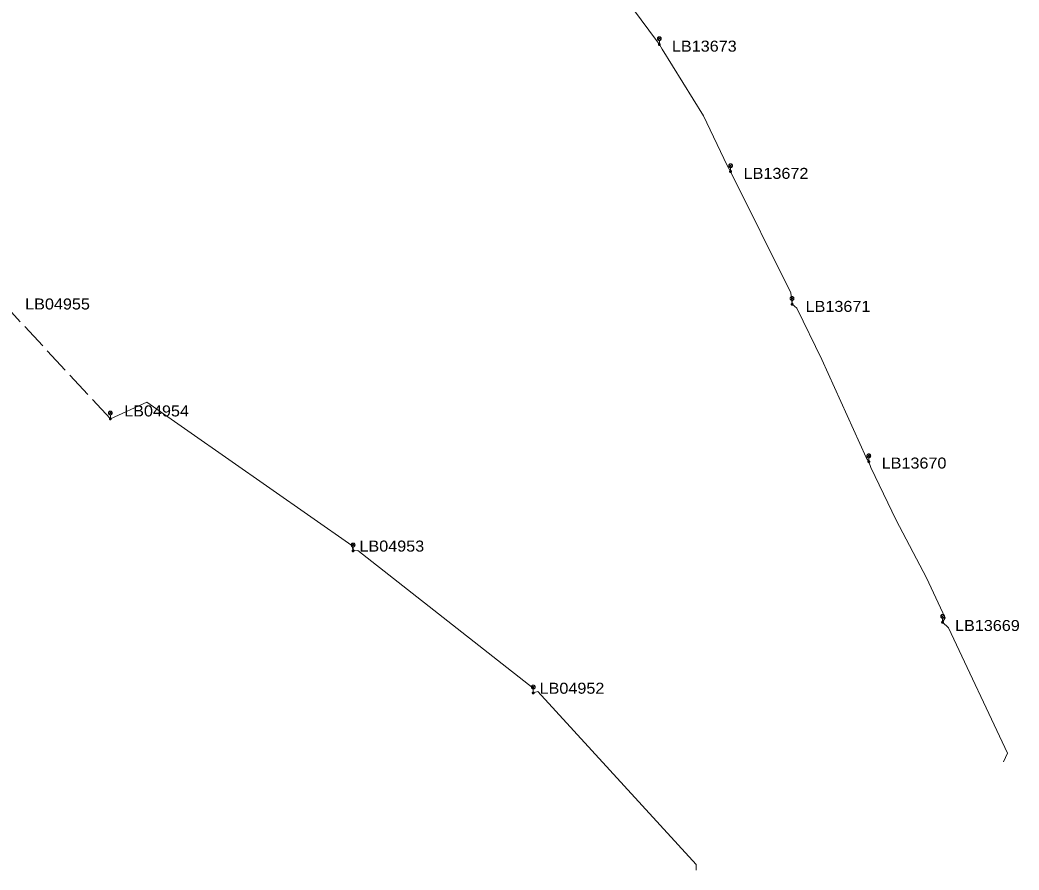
# Model space of a CAD drawing. Extents: x -690018 to -689415, y -972457 to -972107.
# Drawn here: x -689842.5 to -689645.5, y -972456.7 to -972289.3 of the extents above; entities that cross this region are included whole.
import ezdxf

# ---------------------------------------------------------------- set-up
doc = ezdxf.new("R2010")
doc.units = 0
doc.header["$LTSCALE"] = 0.87
doc.linetypes.add('LONG_DASHED', pattern=[7.5, 6, -1.5])
doc.layers.add('1', color=7, linetype='Continuous', lineweight=13)

msp = doc.modelspace()

# ---------------------------------------------------------------- linework, layer by layer
at = {"layer": '1'}
for p, q in [((-689716.685, -972292.665), (-689716.155, -972293.195)), ((-689716.685, -972293.195), (-689716.155, -972292.665)), ((-689716.42, -972294.08), (-689716.42, -972293.305)), ((-689702.635, -972317.705), (-689702.105, -972318.235)), ((-689702.635, -972318.235), (-689702.105, -972317.705)), ((-689702.37, -972319.12), (-689702.37, -972318.345)), ((-689690.515, -972343.865), (-689689.985, -972344.395)), ((-689690.515, -972344.395), (-689689.985, -972343.865)), ((-689690.25, -972345.28), (-689690.25, -972344.505)), ((-689824.905, -972366.425), (-689824.375, -972366.955)), ((-689824.905, -972366.955), (-689824.375, -972366.425)), ((-689824.64, -972367.84), (-689824.64, -972367.065)), ((-689675.395, -972374.875), (-689674.865, -972375.405)), ((-689675.395, -972375.405), (-689674.865, -972374.875)), ((-689675.13, -972376.29), (-689675.13, -972375.515)), ((-689777.048, -972392.422), (-689776.518, -972392.952)), ((-689777.048, -972392.952), (-689776.518, -972392.422)), ((-689776.783, -972393.837), (-689776.783, -972393.062)), ((-689660.845, -972406.495), (-689660.315, -972407.025)), ((-689660.845, -972407.025), (-689660.315, -972406.495)), ((-689660.58, -972407.91), (-689660.58, -972407.135)), ((-689741.535, -972420.425), (-689741.005, -972420.955)), ((-689741.535, -972420.955), (-689741.005, -972420.425)), ((-689741.27, -972421.84), (-689741.27, -972421.065))]:
    msp.add_line(p, q, dxfattribs=at)
at = {"layer": '1', "linetype": 'LONG_DASHED'}
msp.add_line((-689824.64, -972367.84), (-689844.111, -972346.859), dxfattribs=at)
at = {"layer": '1'}
for points in [[(-689736.081, -972268.142), (-689735.301, -972268.549), (-689716.979, -972293.281), (-689716.42, -972294.08)], [(-689716.42, -972294.08), (-689715.873, -972295.023), (-689707.698, -972308.128), (-689703.076, -972317.918), (-689702.37, -972319.12)], [(-689702.37, -972319.12), (-689690.468, -972342.995), (-689690.25, -972345.28)], [(-689690.25, -972345.28), (-689689.336, -972346.046), (-689684.401, -972356.184), (-689675.628, -972375.448), (-689675.13, -972376.29)], [(-689776.783, -972393.837), (-689777.015, -972392.807), (-689817.464, -972364.529), (-689824.64, -972367.84)], [(-689675.13, -972376.29), (-689674.698, -972377.406), (-689669.714, -972387.821), (-689663.787, -972399.156), (-689660.107, -972407.016), (-689660.58, -972407.91)], [(-689741.27, -972421.84), (-689741.27, -972420.888), (-689775.836, -972393.792), (-689776.783, -972393.837)], [(-689660.58, -972407.91), (-689659.447, -972409.021), (-689647.784, -972433.708), (-689648.57, -972435.43)], [(-689709.167, -972456.73), (-689709.167, -972455.675), (-689740.356, -972421.577), (-689741.27, -972421.84)]]:
    msp.add_lwpolyline(points, dxfattribs=at)
for points in [[(-689716.045, -972292.93), (-689716.051, -972292.865), (-689716.068, -972292.802), (-689716.095, -972292.742), (-689716.133, -972292.689), (-689716.179, -972292.643), (-689716.232, -972292.605), (-689716.292, -972292.578), (-689716.355, -972292.561), (-689716.42, -972292.555), (-689716.485, -972292.561), (-689716.548, -972292.578), (-689716.608, -972292.605), (-689716.661, -972292.643), (-689716.707, -972292.689), (-689716.745, -972292.742), (-689716.772, -972292.802), (-689716.789, -972292.865), (-689716.795, -972292.93), (-689716.789, -972292.995), (-689716.772, -972293.058), (-689716.745, -972293.118), (-689716.707, -972293.171), (-689716.661, -972293.217), (-689716.608, -972293.255), (-689716.548, -972293.282), (-689716.485, -972293.299), (-689716.42, -972293.305), (-689716.355, -972293.299), (-689716.292, -972293.282), (-689716.232, -972293.255), (-689716.179, -972293.217), (-689716.133, -972293.171), (-689716.095, -972293.118), (-689716.068, -972293.058), (-689716.051, -972292.995)], [(-689716.23, -972294.08), (-689716.233, -972294.047), (-689716.241, -972294.015), (-689716.255, -972293.985), (-689716.274, -972293.958), (-689716.298, -972293.934), (-689716.325, -972293.915), (-689716.355, -972293.901), (-689716.387, -972293.893), (-689716.42, -972293.89), (-689716.453, -972293.893), (-689716.485, -972293.901), (-689716.515, -972293.915), (-689716.542, -972293.934), (-689716.566, -972293.958), (-689716.585, -972293.985), (-689716.599, -972294.015), (-689716.607, -972294.047), (-689716.61, -972294.08), (-689716.607, -972294.113), (-689716.599, -972294.145), (-689716.585, -972294.175), (-689716.566, -972294.202), (-689716.542, -972294.226), (-689716.515, -972294.245), (-689716.485, -972294.259), (-689716.453, -972294.267), (-689716.42, -972294.27), (-689716.387, -972294.267), (-689716.355, -972294.259), (-689716.325, -972294.245), (-689716.298, -972294.226), (-689716.274, -972294.202), (-689716.255, -972294.175), (-689716.241, -972294.145), (-689716.233, -972294.113)], [(-689716.37, -972294.08), (-689716.371, -972294.071), (-689716.373, -972294.063), (-689716.377, -972294.055), (-689716.382, -972294.048), (-689716.388, -972294.042), (-689716.395, -972294.037), (-689716.403, -972294.033), (-689716.411, -972294.031), (-689716.42, -972294.03), (-689716.429, -972294.031), (-689716.437, -972294.033), (-689716.445, -972294.037), (-689716.452, -972294.042), (-689716.458, -972294.048), (-689716.463, -972294.055), (-689716.467, -972294.063), (-689716.469, -972294.071), (-689716.47, -972294.08), (-689716.469, -972294.089), (-689716.467, -972294.097), (-689716.463, -972294.105), (-689716.458, -972294.112), (-689716.452, -972294.118), (-689716.445, -972294.123), (-689716.437, -972294.127), (-689716.429, -972294.129), (-689716.42, -972294.13), (-689716.411, -972294.129), (-689716.403, -972294.127), (-689716.395, -972294.123), (-689716.388, -972294.118), (-689716.382, -972294.112), (-689716.377, -972294.105), (-689716.373, -972294.097), (-689716.371, -972294.089)], [(-689701.995, -972317.97), (-689702.001, -972317.905), (-689702.018, -972317.842), (-689702.045, -972317.782), (-689702.083, -972317.729), (-689702.129, -972317.683), (-689702.182, -972317.645), (-689702.242, -972317.618), (-689702.305, -972317.601), (-689702.37, -972317.595), (-689702.435, -972317.601), (-689702.498, -972317.618), (-689702.558, -972317.645), (-689702.611, -972317.683), (-689702.657, -972317.729), (-689702.695, -972317.782), (-689702.722, -972317.842), (-689702.739, -972317.905), (-689702.745, -972317.97), (-689702.739, -972318.035), (-689702.722, -972318.098), (-689702.695, -972318.158), (-689702.657, -972318.211), (-689702.611, -972318.257), (-689702.558, -972318.295), (-689702.498, -972318.322), (-689702.435, -972318.339), (-689702.37, -972318.345), (-689702.305, -972318.339), (-689702.242, -972318.322), (-689702.182, -972318.295), (-689702.129, -972318.257), (-689702.083, -972318.211), (-689702.045, -972318.158), (-689702.018, -972318.098), (-689702.001, -972318.035)], [(-689702.18, -972319.12), (-689702.183, -972319.087), (-689702.191, -972319.055), (-689702.205, -972319.025), (-689702.224, -972318.998), (-689702.248, -972318.974), (-689702.275, -972318.955), (-689702.305, -972318.941), (-689702.337, -972318.933), (-689702.37, -972318.93), (-689702.403, -972318.933), (-689702.435, -972318.941), (-689702.465, -972318.955), (-689702.492, -972318.974), (-689702.516, -972318.998), (-689702.535, -972319.025), (-689702.549, -972319.055), (-689702.557, -972319.087), (-689702.56, -972319.12), (-689702.557, -972319.153), (-689702.549, -972319.185), (-689702.535, -972319.215), (-689702.516, -972319.242), (-689702.492, -972319.266), (-689702.465, -972319.285), (-689702.435, -972319.299), (-689702.403, -972319.307), (-689702.37, -972319.31), (-689702.337, -972319.307), (-689702.305, -972319.299), (-689702.275, -972319.285), (-689702.248, -972319.266), (-689702.224, -972319.242), (-689702.205, -972319.215), (-689702.191, -972319.185), (-689702.183, -972319.153)], [(-689702.32, -972319.12), (-689702.321, -972319.111), (-689702.323, -972319.103), (-689702.327, -972319.095), (-689702.332, -972319.088), (-689702.338, -972319.082), (-689702.345, -972319.077), (-689702.353, -972319.073), (-689702.361, -972319.071), (-689702.37, -972319.07), (-689702.379, -972319.071), (-689702.387, -972319.073), (-689702.395, -972319.077), (-689702.402, -972319.082), (-689702.408, -972319.088), (-689702.413, -972319.095), (-689702.417, -972319.103), (-689702.419, -972319.111), (-689702.42, -972319.12), (-689702.419, -972319.129), (-689702.417, -972319.137), (-689702.413, -972319.145), (-689702.408, -972319.152), (-689702.402, -972319.158), (-689702.395, -972319.163), (-689702.387, -972319.167), (-689702.379, -972319.169), (-689702.37, -972319.17), (-689702.361, -972319.169), (-689702.353, -972319.167), (-689702.345, -972319.163), (-689702.338, -972319.158), (-689702.332, -972319.152), (-689702.327, -972319.145), (-689702.323, -972319.137), (-689702.321, -972319.129)], [(-689689.875, -972344.13), (-689689.881, -972344.065), (-689689.898, -972344.002), (-689689.925, -972343.942), (-689689.963, -972343.889), (-689690.009, -972343.843), (-689690.062, -972343.805), (-689690.122, -972343.778), (-689690.185, -972343.761), (-689690.25, -972343.755), (-689690.315, -972343.761), (-689690.378, -972343.778), (-689690.438, -972343.805), (-689690.491, -972343.843), (-689690.537, -972343.889), (-689690.575, -972343.942), (-689690.602, -972344.002), (-689690.619, -972344.065), (-689690.625, -972344.13), (-689690.619, -972344.195), (-689690.602, -972344.258), (-689690.575, -972344.318), (-689690.537, -972344.371), (-689690.491, -972344.417), (-689690.438, -972344.455), (-689690.378, -972344.482), (-689690.315, -972344.499), (-689690.25, -972344.505), (-689690.185, -972344.499), (-689690.122, -972344.482), (-689690.062, -972344.455), (-689690.009, -972344.417), (-689689.963, -972344.371), (-689689.925, -972344.318), (-689689.898, -972344.258), (-689689.881, -972344.195)], [(-689690.06, -972345.28), (-689690.063, -972345.247), (-689690.071, -972345.215), (-689690.085, -972345.185), (-689690.104, -972345.158), (-689690.128, -972345.134), (-689690.155, -972345.115), (-689690.185, -972345.101), (-689690.217, -972345.093), (-689690.25, -972345.09), (-689690.283, -972345.093), (-689690.315, -972345.101), (-689690.345, -972345.115), (-689690.372, -972345.134), (-689690.396, -972345.158), (-689690.415, -972345.185), (-689690.429, -972345.215), (-689690.437, -972345.247), (-689690.44, -972345.28), (-689690.437, -972345.313), (-689690.429, -972345.345), (-689690.415, -972345.375), (-689690.396, -972345.402), (-689690.372, -972345.426), (-689690.345, -972345.445), (-689690.315, -972345.459), (-689690.283, -972345.467), (-689690.25, -972345.47), (-689690.217, -972345.467), (-689690.185, -972345.459), (-689690.155, -972345.445), (-689690.128, -972345.426), (-689690.104, -972345.402), (-689690.085, -972345.375), (-689690.071, -972345.345), (-689690.063, -972345.313)], [(-689690.2, -972345.28), (-689690.201, -972345.271), (-689690.203, -972345.263), (-689690.207, -972345.255), (-689690.212, -972345.248), (-689690.218, -972345.242), (-689690.225, -972345.237), (-689690.233, -972345.233), (-689690.241, -972345.231), (-689690.25, -972345.23), (-689690.259, -972345.231), (-689690.267, -972345.233), (-689690.275, -972345.237), (-689690.282, -972345.242), (-689690.288, -972345.248), (-689690.293, -972345.255), (-689690.297, -972345.263), (-689690.299, -972345.271), (-689690.3, -972345.28), (-689690.299, -972345.289), (-689690.297, -972345.297), (-689690.293, -972345.305), (-689690.288, -972345.312), (-689690.282, -972345.318), (-689690.275, -972345.323), (-689690.267, -972345.327), (-689690.259, -972345.329), (-689690.25, -972345.33), (-689690.241, -972345.329), (-689690.233, -972345.327), (-689690.225, -972345.323), (-689690.218, -972345.318), (-689690.212, -972345.312), (-689690.207, -972345.305), (-689690.203, -972345.297), (-689690.201, -972345.289)], [(-689824.265, -972366.69), (-689824.271, -972366.625), (-689824.288, -972366.562), (-689824.315, -972366.503), (-689824.353, -972366.449), (-689824.399, -972366.403), (-689824.452, -972366.365), (-689824.512, -972366.338), (-689824.575, -972366.321), (-689824.64, -972366.315), (-689824.705, -972366.321), (-689824.768, -972366.338), (-689824.828, -972366.365), (-689824.881, -972366.403), (-689824.927, -972366.449), (-689824.965, -972366.503), (-689824.992, -972366.562), (-689825.009, -972366.625), (-689825.015, -972366.69), (-689825.009, -972366.755), (-689824.992, -972366.818), (-689824.965, -972366.878), (-689824.927, -972366.931), (-689824.881, -972366.977), (-689824.828, -972367.015), (-689824.768, -972367.042), (-689824.705, -972367.059), (-689824.64, -972367.065), (-689824.575, -972367.059), (-689824.512, -972367.042), (-689824.452, -972367.015), (-689824.399, -972366.977), (-689824.353, -972366.931), (-689824.315, -972366.878), (-689824.288, -972366.818), (-689824.271, -972366.755)], [(-689824.45, -972367.84), (-689824.453, -972367.807), (-689824.461, -972367.775), (-689824.475, -972367.745), (-689824.494, -972367.718), (-689824.518, -972367.694), (-689824.545, -972367.675), (-689824.575, -972367.661), (-689824.607, -972367.653), (-689824.64, -972367.65), (-689824.673, -972367.653), (-689824.705, -972367.661), (-689824.735, -972367.675), (-689824.762, -972367.694), (-689824.786, -972367.718), (-689824.805, -972367.745), (-689824.819, -972367.775), (-689824.827, -972367.807), (-689824.83, -972367.84), (-689824.827, -972367.873), (-689824.819, -972367.905), (-689824.805, -972367.935), (-689824.786, -972367.962), (-689824.762, -972367.986), (-689824.735, -972368.005), (-689824.705, -972368.019), (-689824.673, -972368.027), (-689824.64, -972368.03), (-689824.607, -972368.027), (-689824.575, -972368.019), (-689824.545, -972368.005), (-689824.518, -972367.986), (-689824.494, -972367.962), (-689824.475, -972367.935), (-689824.461, -972367.905), (-689824.453, -972367.873)], [(-689824.59, -972367.84), (-689824.591, -972367.831), (-689824.593, -972367.823), (-689824.597, -972367.815), (-689824.602, -972367.808), (-689824.608, -972367.802), (-689824.615, -972367.797), (-689824.623, -972367.793), (-689824.631, -972367.791), (-689824.64, -972367.79), (-689824.649, -972367.791), (-689824.657, -972367.793), (-689824.665, -972367.797), (-689824.672, -972367.802), (-689824.678, -972367.808), (-689824.683, -972367.815), (-689824.687, -972367.823), (-689824.689, -972367.831), (-689824.69, -972367.84), (-689824.689, -972367.849), (-689824.687, -972367.857), (-689824.683, -972367.865), (-689824.678, -972367.872), (-689824.672, -972367.878), (-689824.665, -972367.883), (-689824.657, -972367.887), (-689824.649, -972367.889), (-689824.64, -972367.89), (-689824.631, -972367.889), (-689824.623, -972367.887), (-689824.615, -972367.883), (-689824.608, -972367.878), (-689824.602, -972367.872), (-689824.597, -972367.865), (-689824.593, -972367.857), (-689824.591, -972367.849)], [(-689674.755, -972375.14), (-689674.761, -972375.075), (-689674.778, -972375.012), (-689674.805, -972374.952), (-689674.843, -972374.899), (-689674.889, -972374.853), (-689674.942, -972374.815), (-689675.002, -972374.788), (-689675.065, -972374.771), (-689675.13, -972374.765), (-689675.195, -972374.771), (-689675.258, -972374.788), (-689675.318, -972374.815), (-689675.371, -972374.853), (-689675.417, -972374.899), (-689675.455, -972374.952), (-689675.482, -972375.012), (-689675.499, -972375.075), (-689675.505, -972375.14), (-689675.499, -972375.205), (-689675.482, -972375.268), (-689675.455, -972375.328), (-689675.417, -972375.381), (-689675.371, -972375.427), (-689675.318, -972375.465), (-689675.258, -972375.492), (-689675.195, -972375.509), (-689675.13, -972375.515), (-689675.065, -972375.509), (-689675.002, -972375.492), (-689674.942, -972375.465), (-689674.889, -972375.427), (-689674.843, -972375.381), (-689674.805, -972375.328), (-689674.778, -972375.268), (-689674.761, -972375.205)], [(-689674.94, -972376.29), (-689674.943, -972376.257), (-689674.951, -972376.225), (-689674.965, -972376.195), (-689674.984, -972376.168), (-689675.008, -972376.144), (-689675.035, -972376.125), (-689675.065, -972376.111), (-689675.097, -972376.103), (-689675.13, -972376.1), (-689675.163, -972376.103), (-689675.195, -972376.111), (-689675.225, -972376.125), (-689675.252, -972376.144), (-689675.276, -972376.168), (-689675.295, -972376.195), (-689675.309, -972376.225), (-689675.317, -972376.257), (-689675.32, -972376.29), (-689675.317, -972376.323), (-689675.309, -972376.355), (-689675.295, -972376.385), (-689675.276, -972376.412), (-689675.252, -972376.436), (-689675.225, -972376.455), (-689675.195, -972376.469), (-689675.163, -972376.477), (-689675.13, -972376.48), (-689675.097, -972376.477), (-689675.065, -972376.469), (-689675.035, -972376.455), (-689675.008, -972376.436), (-689674.984, -972376.412), (-689674.965, -972376.385), (-689674.951, -972376.355), (-689674.943, -972376.323)], [(-689675.08, -972376.29), (-689675.081, -972376.281), (-689675.083, -972376.273), (-689675.087, -972376.265), (-689675.092, -972376.258), (-689675.098, -972376.252), (-689675.105, -972376.247), (-689675.113, -972376.243), (-689675.121, -972376.241), (-689675.13, -972376.24), (-689675.139, -972376.241), (-689675.147, -972376.243), (-689675.155, -972376.247), (-689675.162, -972376.252), (-689675.168, -972376.258), (-689675.173, -972376.265), (-689675.177, -972376.273), (-689675.179, -972376.281), (-689675.18, -972376.29), (-689675.179, -972376.299), (-689675.177, -972376.307), (-689675.173, -972376.315), (-689675.168, -972376.322), (-689675.162, -972376.328), (-689675.155, -972376.333), (-689675.147, -972376.337), (-689675.139, -972376.339), (-689675.13, -972376.34), (-689675.121, -972376.339), (-689675.113, -972376.337), (-689675.105, -972376.333), (-689675.098, -972376.328), (-689675.092, -972376.322), (-689675.087, -972376.315), (-689675.083, -972376.307), (-689675.081, -972376.299)], [(-689776.408, -972392.687), (-689776.413, -972392.622), (-689776.43, -972392.559), (-689776.458, -972392.499), (-689776.496, -972392.446), (-689776.542, -972392.4), (-689776.595, -972392.362), (-689776.655, -972392.335), (-689776.718, -972392.318), (-689776.783, -972392.312), (-689776.848, -972392.318), (-689776.911, -972392.335), (-689776.97, -972392.362), (-689777.024, -972392.4), (-689777.07, -972392.446), (-689777.108, -972392.499), (-689777.135, -972392.559), (-689777.152, -972392.622), (-689777.158, -972392.687), (-689777.152, -972392.752), (-689777.135, -972392.815), (-689777.108, -972392.874), (-689777.07, -972392.928), (-689777.024, -972392.974), (-689776.97, -972393.012), (-689776.911, -972393.039), (-689776.848, -972393.056), (-689776.783, -972393.062), (-689776.718, -972393.056), (-689776.655, -972393.039), (-689776.595, -972393.012), (-689776.542, -972392.974), (-689776.496, -972392.928), (-689776.458, -972392.874), (-689776.43, -972392.815), (-689776.413, -972392.752)], [(-689776.593, -972393.837), (-689776.596, -972393.804), (-689776.604, -972393.772), (-689776.618, -972393.742), (-689776.637, -972393.715), (-689776.661, -972393.691), (-689776.688, -972393.672), (-689776.718, -972393.658), (-689776.75, -972393.65), (-689776.783, -972393.647), (-689776.816, -972393.65), (-689776.848, -972393.658), (-689776.878, -972393.672), (-689776.905, -972393.691), (-689776.928, -972393.715), (-689776.947, -972393.742), (-689776.961, -972393.772), (-689776.97, -972393.804), (-689776.973, -972393.837), (-689776.97, -972393.87), (-689776.961, -972393.902), (-689776.947, -972393.932), (-689776.928, -972393.959), (-689776.905, -972393.982), (-689776.878, -972394.001), (-689776.848, -972394.015), (-689776.816, -972394.024), (-689776.783, -972394.027), (-689776.75, -972394.024), (-689776.718, -972394.015), (-689776.688, -972394.001), (-689776.661, -972393.982), (-689776.637, -972393.959), (-689776.618, -972393.932), (-689776.604, -972393.902), (-689776.596, -972393.87)], [(-689776.733, -972393.837), (-689776.734, -972393.828), (-689776.736, -972393.82), (-689776.739, -972393.812), (-689776.744, -972393.805), (-689776.751, -972393.799), (-689776.758, -972393.794), (-689776.766, -972393.79), (-689776.774, -972393.788), (-689776.783, -972393.787), (-689776.791, -972393.788), (-689776.8, -972393.79), (-689776.808, -972393.794), (-689776.815, -972393.799), (-689776.821, -972393.805), (-689776.826, -972393.812), (-689776.83, -972393.82), (-689776.832, -972393.828), (-689776.833, -972393.837), (-689776.832, -972393.846), (-689776.83, -972393.854), (-689776.826, -972393.862), (-689776.821, -972393.869), (-689776.815, -972393.875), (-689776.808, -972393.88), (-689776.8, -972393.884), (-689776.791, -972393.886), (-689776.783, -972393.887), (-689776.774, -972393.886), (-689776.766, -972393.884), (-689776.758, -972393.88), (-689776.751, -972393.875), (-689776.744, -972393.869), (-689776.739, -972393.862), (-689776.736, -972393.854), (-689776.734, -972393.846)], [(-689660.205, -972406.76), (-689660.211, -972406.695), (-689660.228, -972406.632), (-689660.255, -972406.572), (-689660.293, -972406.519), (-689660.339, -972406.473), (-689660.392, -972406.435), (-689660.452, -972406.408), (-689660.515, -972406.391), (-689660.58, -972406.385), (-689660.645, -972406.391), (-689660.708, -972406.408), (-689660.768, -972406.435), (-689660.821, -972406.473), (-689660.867, -972406.519), (-689660.905, -972406.572), (-689660.932, -972406.632), (-689660.949, -972406.695), (-689660.955, -972406.76), (-689660.949, -972406.825), (-689660.932, -972406.888), (-689660.905, -972406.948), (-689660.867, -972407.001), (-689660.821, -972407.047), (-689660.768, -972407.085), (-689660.708, -972407.112), (-689660.645, -972407.129), (-689660.58, -972407.135), (-689660.515, -972407.129), (-689660.452, -972407.112), (-689660.392, -972407.085), (-689660.339, -972407.047), (-689660.293, -972407.001), (-689660.255, -972406.948), (-689660.228, -972406.888), (-689660.211, -972406.825)], [(-689660.39, -972407.91), (-689660.393, -972407.877), (-689660.401, -972407.845), (-689660.415, -972407.815), (-689660.434, -972407.788), (-689660.458, -972407.764), (-689660.485, -972407.745), (-689660.515, -972407.731), (-689660.547, -972407.723), (-689660.58, -972407.72), (-689660.613, -972407.723), (-689660.645, -972407.731), (-689660.675, -972407.745), (-689660.702, -972407.764), (-689660.726, -972407.788), (-689660.745, -972407.815), (-689660.759, -972407.845), (-689660.767, -972407.877), (-689660.77, -972407.91), (-689660.767, -972407.943), (-689660.759, -972407.975), (-689660.745, -972408.005), (-689660.726, -972408.032), (-689660.702, -972408.056), (-689660.675, -972408.075), (-689660.645, -972408.089), (-689660.613, -972408.097), (-689660.58, -972408.1), (-689660.547, -972408.097), (-689660.515, -972408.089), (-689660.485, -972408.075), (-689660.458, -972408.056), (-689660.434, -972408.032), (-689660.415, -972408.005), (-689660.401, -972407.975), (-689660.393, -972407.943)], [(-689660.53, -972407.91), (-689660.531, -972407.901), (-689660.533, -972407.893), (-689660.537, -972407.885), (-689660.542, -972407.878), (-689660.548, -972407.872), (-689660.555, -972407.867), (-689660.563, -972407.863), (-689660.571, -972407.861), (-689660.58, -972407.86), (-689660.589, -972407.861), (-689660.597, -972407.863), (-689660.605, -972407.867), (-689660.612, -972407.872), (-689660.618, -972407.878), (-689660.623, -972407.885), (-689660.627, -972407.893), (-689660.629, -972407.901), (-689660.63, -972407.91), (-689660.629, -972407.919), (-689660.627, -972407.927), (-689660.623, -972407.935), (-689660.618, -972407.942), (-689660.612, -972407.948), (-689660.605, -972407.953), (-689660.597, -972407.957), (-689660.589, -972407.959), (-689660.58, -972407.96), (-689660.571, -972407.959), (-689660.563, -972407.957), (-689660.555, -972407.953), (-689660.548, -972407.948), (-689660.542, -972407.942), (-689660.537, -972407.935), (-689660.533, -972407.927), (-689660.531, -972407.919)], [(-689740.895, -972420.69), (-689740.901, -972420.625), (-689740.918, -972420.562), (-689740.945, -972420.503), (-689740.983, -972420.449), (-689741.029, -972420.403), (-689741.082, -972420.365), (-689741.142, -972420.338), (-689741.205, -972420.321), (-689741.27, -972420.315), (-689741.335, -972420.321), (-689741.398, -972420.338), (-689741.458, -972420.365), (-689741.511, -972420.403), (-689741.557, -972420.449), (-689741.595, -972420.503), (-689741.622, -972420.562), (-689741.639, -972420.625), (-689741.645, -972420.69), (-689741.639, -972420.755), (-689741.622, -972420.818), (-689741.595, -972420.878), (-689741.557, -972420.931), (-689741.511, -972420.977), (-689741.458, -972421.015), (-689741.398, -972421.042), (-689741.335, -972421.059), (-689741.27, -972421.065), (-689741.205, -972421.059), (-689741.142, -972421.042), (-689741.082, -972421.015), (-689741.029, -972420.977), (-689740.983, -972420.931), (-689740.945, -972420.878), (-689740.918, -972420.818), (-689740.901, -972420.755)], [(-689741.08, -972421.84), (-689741.083, -972421.807), (-689741.091, -972421.775), (-689741.105, -972421.745), (-689741.124, -972421.718), (-689741.148, -972421.694), (-689741.175, -972421.675), (-689741.205, -972421.661), (-689741.237, -972421.653), (-689741.27, -972421.65), (-689741.303, -972421.653), (-689741.335, -972421.661), (-689741.365, -972421.675), (-689741.392, -972421.694), (-689741.416, -972421.718), (-689741.435, -972421.745), (-689741.449, -972421.775), (-689741.457, -972421.807), (-689741.46, -972421.84), (-689741.457, -972421.873), (-689741.449, -972421.905), (-689741.435, -972421.935), (-689741.416, -972421.962), (-689741.392, -972421.986), (-689741.365, -972422.005), (-689741.335, -972422.019), (-689741.303, -972422.027), (-689741.27, -972422.03), (-689741.237, -972422.027), (-689741.205, -972422.019), (-689741.175, -972422.005), (-689741.148, -972421.986), (-689741.124, -972421.962), (-689741.105, -972421.935), (-689741.091, -972421.905), (-689741.083, -972421.873)], [(-689741.22, -972421.84), (-689741.221, -972421.831), (-689741.223, -972421.823), (-689741.227, -972421.815), (-689741.232, -972421.808), (-689741.238, -972421.802), (-689741.245, -972421.797), (-689741.253, -972421.793), (-689741.261, -972421.791), (-689741.27, -972421.79), (-689741.279, -972421.791), (-689741.287, -972421.793), (-689741.295, -972421.797), (-689741.302, -972421.802), (-689741.308, -972421.808), (-689741.313, -972421.815), (-689741.317, -972421.823), (-689741.319, -972421.831), (-689741.32, -972421.84), (-689741.319, -972421.849), (-689741.317, -972421.857), (-689741.313, -972421.865), (-689741.308, -972421.872), (-689741.302, -972421.878), (-689741.295, -972421.883), (-689741.287, -972421.887), (-689741.279, -972421.889), (-689741.27, -972421.89), (-689741.261, -972421.889), (-689741.253, -972421.887), (-689741.245, -972421.883), (-689741.238, -972421.878), (-689741.232, -972421.872), (-689741.227, -972421.865), (-689741.223, -972421.857), (-689741.221, -972421.849)]]:
    msp.add_lwpolyline(points, close=True, dxfattribs=at)

# ---------------------------------------------------------------- texts
at = {"layer": '1', "width": 1.1}
for s, p in [('LB13673', (-689713.935, -972295.503)), ('LB13672', (-689699.802, -972320.565)), ('LB04955', (-689841.433, -972346.302)), ('LB13671', (-689687.588, -972346.774)), ('LB04954', (-689821.91, -972367.368)), ('LB13670', (-689672.592, -972377.638)), ('LB04953', (-689775.537, -972393.997)), ('LB13669', (-689658.128, -972409.646)), ('LB04952', (-689740.024, -972422))]:
    msp.add_text(s, height=2.167, dxfattribs=at).set_placement(p)

doc.saveas('drawing.dxf')
